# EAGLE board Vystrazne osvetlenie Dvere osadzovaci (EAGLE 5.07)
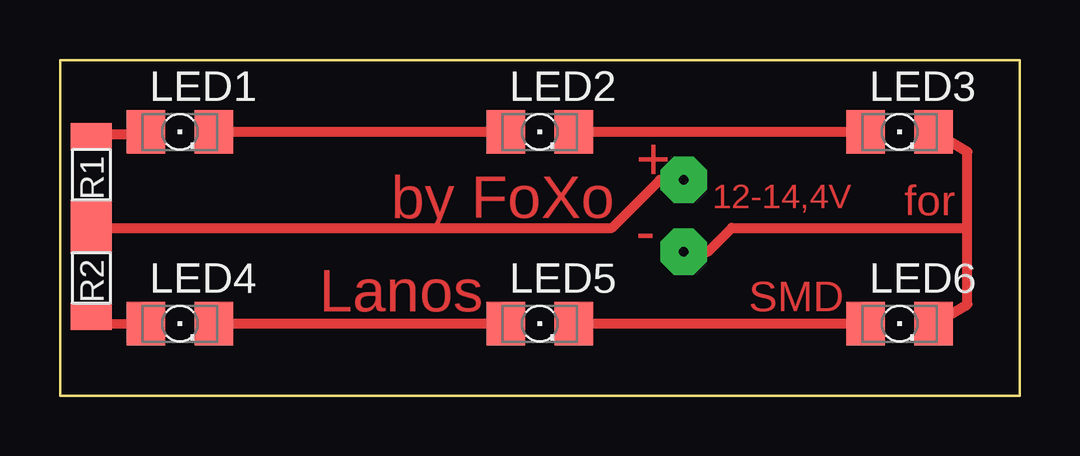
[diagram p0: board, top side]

Size 40 x 14 mm. Coordinates in mm from the lower left corner, seen from the top.
Outline: 0,0 40,0 40,14 0,14 0,0
Copper layers (1*16): Top 0.035mm / dielectric 1.5mm / Bottom 0.035mm
Design rules "default": minimum track width 10mil, minimum drill 24mil, track to track 8mil, track to pad 8mil, pad to pad 8mil, via to via 8mil, smd to smd 8mil, copper to edge 40mil, drill to drill 8mil, minimum pad ring 10mil, minimum via ring 8mil, stop-mask expansion 4mil, vias tented up to drill 0mil, thermal gap 10mil

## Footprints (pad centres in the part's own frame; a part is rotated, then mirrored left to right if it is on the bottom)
1206 = smd 1.6 x 1.803: A -1.422,0; C 1.422,0
1206' = smd 1.143 x 1.702: 1 -1.587,0; 2 1.587,0

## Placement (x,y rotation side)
LED1  [1206]  5,11 0 top
LED2  [1206]  20,11 0 top
LED3  [1206]  35,11 0 top
LED4  [1206]  5,3 0 top
LED5  [1206]  20,3 0 top
LED6  [1206]  35,3 0 top
R1  [1206']  1.3,9.2 270 top
R2  [1206']  1.3,4.9 270 top

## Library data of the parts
LED1-LED6 = led
R1 R2 = #PaJa_21

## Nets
S$1: LED3.C LED6.C
S$6: LED4.A
S$7: LED2.C
S$9: LED3.A
S$12: LED1.C

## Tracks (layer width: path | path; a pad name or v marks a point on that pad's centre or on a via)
S$1
  Top 0.406: LED6.C 37.83,3.81 37.83,10.16 LED3.C
S$2
  Top 0.406: 1.9,10.9 3,10.9
S$6
  Top 0.406: 1.91,3.01 LED4.A
S$7
  Top 0.254: LED2.C 21.59,11.43
S$9
  Top 0.254: LED3.A 33.02,11.43
S$10  (via drill 0.4 pad 1.93)
  Top 0.406: v26,9 25,9 23,7 1.9,7
S$11  (via drill 0.4 pad 1.93)
  Top 0.406: v26,6 27,6 28,7 37.8,7
S$12
  Top 0.254: LED1.C 6.35,11.43
S$14
  Top 0.406: 18,3 7,3
S$15
  Top 0.406: 33,3 22,3
S$16
  Top 0.406: 33,11 22,11
S$17
  Top 0.406: 18,11 7,11

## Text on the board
Top: + | 12-14,4V | for | by FoXo | - | Lanos | SMD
